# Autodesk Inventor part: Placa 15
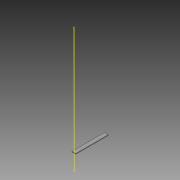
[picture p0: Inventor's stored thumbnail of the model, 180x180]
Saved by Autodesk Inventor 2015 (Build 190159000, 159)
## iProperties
Created: 2015-04
Part Number: Placa 15
Material: Generic
Document SubType Name: Modeling
Designer: suporte
Density: 1 g/cm^3
Appearance: Default
Author: suporte
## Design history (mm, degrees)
workplane "Work Plane1"
sketch "Sketch1"
  geometry: L1 (-21.869, 0)-(-21.869, 2100) reference; L2 (-27.717, 1900)-(46.683, 1900) reference; L3 (47.283, 0)-(47.283, 2100) reference; L4 (19.566, 1912.5)-(0, 1912.5) reference; L5 (47.283, 1900)-(-27.717, 1900); L6 (-27.717, 1900)-(-27.717, 1912.5); L7 (-27.717, 1912.5)-(47.283, 1912.5); L8 (47.283, 1912.5)-(47.283, 1900); L9 (-27.717, 0)-(-27.717, 2100) reference
  constraints: 10 end point, 3 point on line, 2 parallel, 1 horizontal, 1 perpendicular, 1 vertical, 2 other
  node "Reference1"
  node "Reference2"
  node "Reference3"
  node "Reference4"
workplane "Work Plane2"
extrude "Extrusion1" new body sketch "Sketch1" stored distance "d0" = 10; taper "d1" = 0 deg
body "Solid1"
